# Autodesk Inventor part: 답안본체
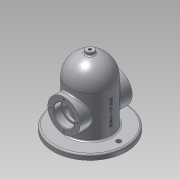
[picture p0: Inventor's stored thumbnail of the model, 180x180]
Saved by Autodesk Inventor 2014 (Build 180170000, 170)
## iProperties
Created: 2019-11
Part Number: 답안본체
Material: 알루미늄 6061
Document SubType Name: Modeling
Designer: net
Density: 2.71 g/cm^3
Appearance: 알루미늄 - 평지
Mass: 1110.21 g
Surface Area: 883.587 cm^2
Volume: 409.671 cm^3
Author: net
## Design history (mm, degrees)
sketch "스케치1"
  geometry: C1 r 40 at (0, 0); 1 further point
  constraints: 1 centre point, 1 coincident
  dimensions: "d0" = 80 diameter of C1
extrude "돌출1" new body sketch "스케치1" distance "d1" = 90; taper "d2" = 0 deg
sketch "스케치2"
  geometry: L1 (40, 90)-(-40, 90) reference; L2 (0, 90)-(0, 130); A1 r 40 centre (0, 90) between (0, 130) and (-40, 90); 1 further point
  constraints: 2 end point, 2 point on circle, 1 centre point, 1 midpoint, 1 perpendicular
  dimensions: "d3" = 40 distance of L2.start L2.end; "d4" = 40 radius of A1
revolve "회전1" sketch "스케치2" stored, may be unused: angle "d5" = 90 deg
sketch "스케치4"
  geometry: L1 (40, 90)-(-40, 90) reference; L2 (0, 90)-(0, 120); A1 r 30 centre (0, 90) between (0, 120) and (-30, 90); 1 further point
  constraints: 2 end point, 2 point on circle, 1 centre point, 1 coincident, 1 midpoint, 1 point on line, 1 vertical
  dimensions: "d9" = 30 distance of L2.start L2.end; "d10" = 30 radius of A1
revolve "회전2" sketch "스케치4" stored, may be unused: angle "d11" = 90 deg
sketch "스케치6"
  geometry: C1 r 31 at (0, 50); 1 further point
  constraints: 1 centre point, 1 vertical alignment
  dimensions: "d12" = 50 distance of point (0, 0) C1.centre; "d13" = 62 diameter of C1
extrude "돌출3" join sketch "스케치6" distance "d14" = 50; taper "d16" = 0 deg; dims "d15" = 50, "d17" = 0
sketch "스케치7"
  geometry: C1 r 40 at (0, 0) reference; C2 r 30 at (0, 0)
  constraints: 1 centre point, 1 coincident
  dimensions: "d18" = 60 diameter of C2
extrude "돌출4" cut sketch "스케치7" distance "d19" = 90; taper "d20" = 0 deg
sketch "스케치8"
  geometry: C1 r 31 at (0, 0) reference; C2 r 20 at (0, 0); 1 further point
  constraints: 1 centre point, 1 coincident
  dimensions: "d21" = 40 diameter of C2
extrude "돌출5" cut sketch "스케치8" distance "d22" = 15; taper "d23" = 0 deg
sketch "스케치9"
  geometry: C1 r 31 at (0, 0) reference; C2 r 20 at (0, 0); 1 further point
  constraints: 1 centre point, 1 coincident
  dimensions: "d24" = 40 diameter of C2
extrude "돌출6" cut sketch "스케치9" distance "d25" = 15; taper "d26" = 0 deg
sketch "스케치10"
  geometry: C1 r 20 at (0, 0) reference; C2 r 16.5 at (0, 0); 1 further point
  constraints: 1 centre point, 1 coincident
  dimensions: "d27" = 33 diameter of C2
extrude "돌출7" cut sketch "스케치10" distance "d28" = 90; taper "d29" = 0 deg
sketch "스케치11"
  geometry: C1 r 40 at (0, 0) reference; C2 r 70 at (0, 0); 1 further point
  constraints: 1 centre point, 1 coincident
  dimensions: "d30" = 140 diameter of C2
extrude "돌출8" join sketch "스케치11" distance "d31" = 10; taper "d32" = 0 deg
sketch "스케치12"
  geometry: C1 r 20 at (0, 0) reference; 2 further points
  constraints: 1 vertical alignment
  dimensions: "d33" = 26 distance of point (0, 26) C1.centre
hole "구멍1" sketch "스케치12" at (0, 26) diameter "d34" = 3.242; stored, may be unused: countersink angle "d38" = 90 deg, drill point angle "d40" = 118 deg; dims "d35" = 8, "d36" = 4, "d37" = 2, "d39" = 10
node "작업 평면1"
sketch "스케치13"
  geometry: C1 r 7.5 at (0, 0); 1 further point
  constraints: 1 centre point, 1 coincident
  dimensions: "d45" = 15 diameter of C1
extrude "돌출9" join sketch "스케치13" stored distance "d46" = 10; taper "d47" = 0 deg
hole "구멍2" diameter "d50" = 5.188; stored, may be unused: countersink angle "d54" = 90 deg, drill point angle "d56" = 118 deg; dims "d48" = 10, "d49" = 10, "d51" = 20, "d52" = 4, "d53" = 2, "d55" = 20
sketch "스케치14"
  geometry: C1 r 40 at (0, 0) reference; 2 further points
  constraints: 2 horizontal alignment
  dimensions: "d57" = 55 distance of C1.centre point (55, 0); "d58" = 55 distance of point (-55, 0) C1.centre
hole "구멍3" sketch "스케치14" at (55, 0), (-55, 0) diameter "d59" = 9; stored, may be unused: countersink angle "d63" = 90 deg, drill point angle "d65" = 118 deg; dims "d60" = 20, "d61" = 4, "d62" = 2, "d64" = 20
node "작업 평면2"
sketch "스케치15"
  geometry: L1 (-70, 0)-(70, 0) reference; 3 further points
  constraints: 1 midpoint, 1 vertical alignment, 1 other
  dimensions: "d67" = 50 distance from line of point (0, 50) L1
feature "엠보싱1" sketch "스케치15" dims "d16" = 0, "d68" = 0.5, "d69" = 0
fillet "모깎기1" dims "d70" = 3
fillet "모깎기2" dims "d71" = 3
chamfer "모따기1" distance "d72" = 1; stored, may be unused: second distance "d73" = 2, angle "d74" = 45 deg
fillet "모깎기3" dims "d75" = 0.3
node "솔리드1"
pattern_circular "원형 패턴1" dims angle "d42" = 360 deg
mirror "대칭1"
other parameters: "d44" = 135
